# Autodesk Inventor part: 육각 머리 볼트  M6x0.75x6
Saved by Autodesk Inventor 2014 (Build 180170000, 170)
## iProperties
Created: 2024-05
Part Number: 육각 머리 볼트  M6x0.75x6
Material: 일반
Document SubType Name: Modeling
Designer: dg
Density: 1 g/cm^3
Appearance: 기본값
Author: dg
Author: jhkim
Description: 6각 머리 볼트 및 6각 머리 나사
Creation Date: 2024-05-10
Sending System: Autodesk Inventor 2025
Preprocessor: ST-DEVELOPER v20
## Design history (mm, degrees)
node "육각 머리 볼트  M6x0.75x61"
body "Solid1"
node "기준1"
